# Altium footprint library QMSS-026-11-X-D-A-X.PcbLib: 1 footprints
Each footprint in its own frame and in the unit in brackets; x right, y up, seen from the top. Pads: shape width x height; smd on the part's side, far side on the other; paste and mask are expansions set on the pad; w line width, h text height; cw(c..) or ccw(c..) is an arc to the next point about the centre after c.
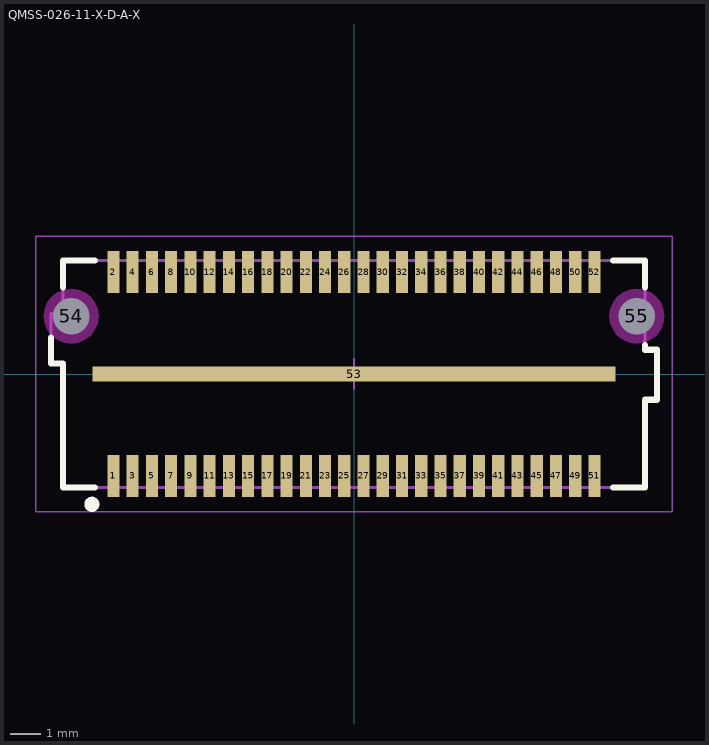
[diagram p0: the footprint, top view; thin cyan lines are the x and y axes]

## QMSS-026-11-X-D-A-X [mm] "0.635mm pitch, 52 pin, high speed shielded terminal"
height 6.35
pads (55):
  rect 0.4x1.4 smd mask+0: 1(-7.94,-3.365) 2(-7.94,3.365) 3(-7.305,-3.365) 4(-7.305,3.365) 5(-6.67,-3.365) 6(-6.67,3.365) 7(-6.035,-3.365) 8(-6.035,3.365) 9(-5.4,-3.365) 10(-5.4,3.365) 11(-4.765,-3.365) 12(-4.765,3.365) 13(-4.13,-3.365) 14(-4.13,3.365) 15(-3.495,-3.365) 16(-3.495,3.365) 17(-2.86,-3.365) 18(-2.86,3.365) 19(-2.225,-3.365) 20(-2.225,3.365) 21(-1.59,-3.365) 22(-1.59,3.365) 23(-0.955,-3.365) 24(-0.955,3.365) 25(-0.32,-3.365) 26(-0.32,3.365) 27(0.315,-3.365) 28(0.315,3.365) 29(0.95,-3.365) 30(0.95,3.365) 31(1.585,-3.365) 32(1.585,3.365) 33(2.22,-3.365) 34(2.22,3.365) 35(2.855,-3.365) 36(2.855,3.365) 37(3.49,-3.365) 38(3.49,3.365) 39(4.125,-3.365) 40(4.125,3.365) 41(4.76,-3.365) 42(4.76,3.365) 43(5.395,-3.365) 44(5.395,3.365) 45(6.03,-3.365) 46(6.03,3.365) 47(6.665,-3.365) 48(6.665,3.365) 49(7.3,-3.365) 50(7.3,3.365) 51(7.935,-3.365) 52(7.935,3.365)
  rect 17.25x0.5 smd mask+0: 53(0,0)
  round 1 hole 1.2 unplated mask+0: 54(-9.335,1.91) 55(9.335,1.91)
Top Overlay:
  circle w0.25: c-8.65,-4.3 r0.125
  lines w0.2: -10,1.2 -10,0.35 -9.6,0.35 -9.6,-3.75 -8.55,-3.75 ; -9.6,2.85 -9.6,3.75 -8.55,3.75 ; 8.55,-3.75 9.6,-3.75 9.6,-0.85 10,-0.85 10,0.8 9.6,0.8 9.6,0.95 ; 8.55,3.75 9.6,3.75 9.6,2.85
Keep-Out Layer:
  pour cut-out: 10.243,1.91 10.212,2.145 10.121,2.364 9.977,2.552 9.789,2.696 9.57,2.787 9.335,2.818 9.1,2.787 8.881,2.696 8.693,2.552 8.549,2.364 8.458,2.145 8.427,1.91 8.458,1.675 8.549,1.456 8.693,1.268 8.881,1.124 9.1,1.033 9.335,1.002 9.57,1.033 9.789,1.124 9.977,1.268 10.121,1.456 10.212,1.675
  pour cut-out: -8.427,1.91 -8.458,2.145 -8.549,2.364 -8.693,2.552 -8.881,2.696 -9.1,2.787 -9.335,2.818 -9.57,2.787 -9.789,2.696 -9.977,2.552 -10.121,2.364 -10.212,2.145 -10.243,1.91 -10.212,1.675 -10.121,1.456 -9.977,1.268 -9.789,1.124 -9.57,1.033 -9.335,1.002 -9.1,1.033 -8.881,1.124 -8.693,1.268 -8.549,1.456 -8.458,1.675
Mechanical 12:
  lines w0.001: -10,0.35 -10,2 -9.6,2 -9.6,3.75 9.6,3.75 9.6,0.8 10,0.8 10,-0.85 9.6,-0.85 9.6,-3.75 -9.6,-3.75 -9.6,0.35 -10,0.35
Mechanical 13:
  lines w0.1: -10,0.35 -10,2 -9.6,2 -9.6,3.75 9.6,3.75 9.6,0.8 10,0.8 10,-0.85 9.6,-0.85 9.6,-3.75 -9.6,-3.75 -9.6,0.35 -10,0.35
  text ".Designator" at 0.254,0.254 h1.52
Mechanical 15:
  lines w0.05: -0.5,0 0.5,0 ; 0,-0.5 0,0.5 ; -10.5,-4.55 -10.5,4.55 10.5,4.55 10.5,-4.55 -10.5,-4.55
